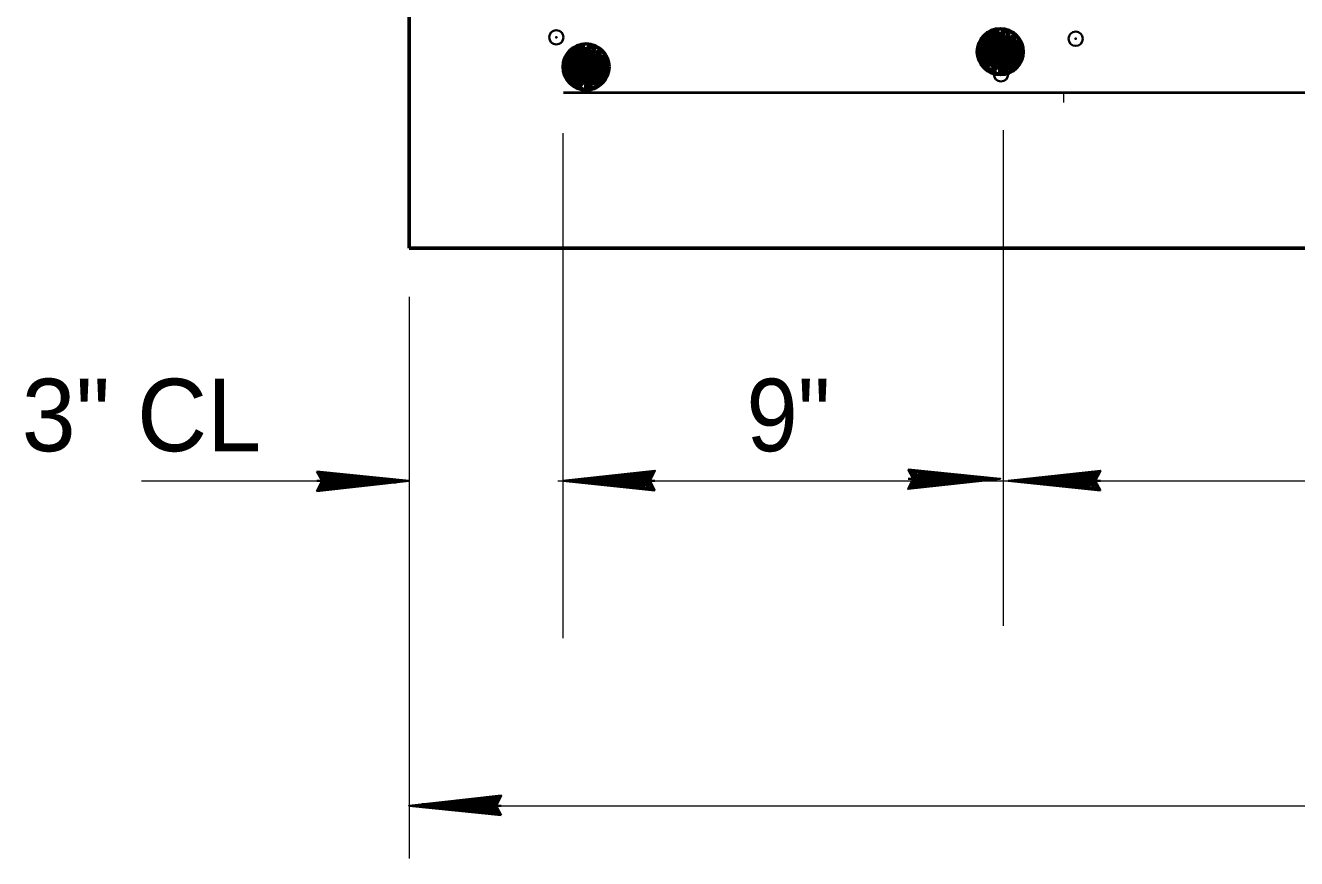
# Model space of a CAD drawing. Extents: x 4.49 to 7.69, y 0.28 to 2.27.
# Drawn here: x 5.8123 to 5.9583, y 1.8022 to 1.898 of the extents above; entities that cross this region are included whole.
import ezdxf
from ezdxf.enums import TextEntityAlignment as Align

# ---------------------------------------------------------------- set-up
doc = ezdxf.new("R2010")
doc.units = 0
doc.header["$LTSCALE"] = 0.0033
doc.header["$PDMODE"] = 32
doc.header["$PDSIZE"] = 0.00165
doc.layers.add('1', color=7, linetype='Continuous', lineweight=35)

msp = doc.modelspace()

# ---------------------------------------------------------------- linework, layer by layer
at = {"layer": '1', "lineweight": 60}
for p, q in [((5.856333, 1.872333), (5.856333, 1.955667)), ((5.922417, 1.8965), (5.92225, 1.893583)), ((5.922667, 1.8965), (5.922417, 1.893583)), ((5.922833, 1.8965), (5.922667, 1.8935)), ((5.923, 1.8965), (5.92275, 1.8935)), ((5.923167, 1.8965), (5.923, 1.8935)), ((5.923417, 1.8965), (5.92325, 1.8935)), ((5.923667, 1.8965), (5.923417, 1.8935)), ((5.92375, 1.896417), (5.923583, 1.8935)), ((5.923917, 1.896417), (5.92375, 1.8935)), ((5.924083, 1.896417), (5.923917, 1.8935)), ((5.924333, 1.896417), (5.924083, 1.8935)), ((5.9245, 1.896417), (5.924333, 1.8935)), ((5.92475, 1.896333), (5.9245, 1.893417)), ((5.925, 1.896333), (5.92475, 1.893417)), ((5.925167, 1.896333), (5.925, 1.893417)), ((5.92525, 1.896333), (5.925083, 1.893417)), ((5.925417, 1.896333), (5.92525, 1.893417)), ((5.9255, 1.896333), (5.925333, 1.893417)), ((5.92575, 1.89625), (5.9255, 1.893333)), ((5.925917, 1.89625), (5.92575, 1.893333)), ((5.926083, 1.89625), (5.925833, 1.893333)), ((5.92625, 1.89625), (5.926083, 1.893333)), ((5.9265, 1.89625), (5.926333, 1.893333)), ((5.92675, 1.894333), (5.926583, 1.896167)), ((5.874833, 1.89475), (5.874667, 1.891833)), ((5.875083, 1.89475), (5.874833, 1.891833)), ((5.87525, 1.89475), (5.875083, 1.89175)), ((5.875417, 1.89475), (5.875167, 1.89175)), ((5.875583, 1.89475), (5.875417, 1.89175)), ((5.875833, 1.89475), (5.875667, 1.89175)), ((5.876083, 1.89475), (5.875833, 1.89175)), ((5.876167, 1.894667), (5.876, 1.89175)), ((5.876333, 1.894667), (5.876167, 1.89175)), ((5.8765, 1.894667), (5.876333, 1.89175)), ((5.87675, 1.894667), (5.8765, 1.89175)), ((5.876917, 1.894667), (5.87675, 1.89175)), ((5.877167, 1.894583), (5.876917, 1.891667)), ((5.877417, 1.894583), (5.877167, 1.891667)), ((5.877583, 1.894583), (5.877417, 1.891667)), ((5.877667, 1.894583), (5.8775, 1.891667)), ((5.877833, 1.894583), (5.877667, 1.891667)), ((5.877917, 1.894583), (5.87775, 1.891667)), ((5.878167, 1.8945), (5.877917, 1.891583)), ((5.878333, 1.8945), (5.878167, 1.891583)), ((5.8785, 1.8945), (5.87825, 1.891583)), ((5.878667, 1.8945), (5.8785, 1.891583)), ((5.878917, 1.8945), (5.87875, 1.891583)), ((5.879167, 1.892583), (5.879, 1.894417)), ((5.92675, 1.894333), (5.922, 1.893583)), ((5.879167, 1.892583), (5.874417, 1.891833))]:
    msp.add_line(p, q, dxfattribs=at)
at = {"layer": '1', "lineweight": 40}
for p, q in [((5.9245, 1.896), (5.925833, 1.897)), ((5.926583, 1.896167), (5.925333, 1.897333)), ((5.879, 1.894417), (5.87775, 1.895583)), ((5.922167, 1.8965), (5.92675, 1.894333)), ((5.922417, 1.896083), (5.926333, 1.895333)), ((5.922417, 1.895917), (5.926333, 1.895167)), ((5.922417, 1.895667), (5.92625, 1.894917)), ((5.9225, 1.8965), (5.926417, 1.895833)), ((5.9225, 1.896333), (5.926417, 1.895583)), ((5.922583, 1.896833), (5.926417, 1.896167)), ((5.874583, 1.89475), (5.879167, 1.892583)), ((5.874833, 1.894333), (5.87875, 1.893583)), ((5.874833, 1.894167), (5.87875, 1.893417)), ((5.874917, 1.89475), (5.878833, 1.894083)), ((5.874917, 1.894583), (5.878833, 1.893833)), ((5.875, 1.895083), (5.878833, 1.894417)), ((5.876917, 1.89425), (5.87825, 1.89525)), ((5.922083, 1.89425), (5.926, 1.8935)), ((5.922083, 1.894083), (5.925917, 1.893333)), ((5.922167, 1.894667), (5.926083, 1.893917)), ((5.92225, 1.895083), (5.926083, 1.894333)), ((5.92225, 1.894917), (5.926083, 1.894167)), ((5.922333, 1.8955), (5.926167, 1.894833)), ((5.922333, 1.895333), (5.926167, 1.894583)), ((5.874583, 1.892917), (5.8785, 1.892167)), ((5.874667, 1.893333), (5.8785, 1.892583)), ((5.874667, 1.893167), (5.8785, 1.892417)), ((5.87475, 1.89375), (5.878583, 1.893083)), ((5.87475, 1.893583), (5.878583, 1.892833)), ((5.874833, 1.893917), (5.878667, 1.893167)), ((5.922, 1.89375), (5.925833, 1.893)), ((5.922, 1.893583), (5.925833, 1.892833)), ((5.922083, 1.893833), (5.925917, 1.893167)), ((5.926333, 1.893333), (5.922583, 1.892917)), ((5.874417, 1.892), (5.87825, 1.89125)), ((5.874417, 1.891833), (5.87825, 1.891083)), ((5.8745, 1.8925), (5.878417, 1.89175)), ((5.8745, 1.892333), (5.878333, 1.891583)), ((5.8745, 1.892083), (5.878333, 1.891417)), ((5.87875, 1.891583), (5.875, 1.891167)), ((5.874083, 1.89025), (6.17175, 1.89025))]:
    msp.add_line(p, q, dxfattribs=at)
at = {"layer": '1', "lineweight": 13}
for p, q in [((5.9315, 1.89025), (5.9315, 1.889083)), ((5.874, 1.885583), (5.874, 1.8275)), ((5.924583, 1.885917), (5.924583, 1.828917)), ((5.856333, 1.86675), (5.856333, 1.802167)), ((5.825583, 1.845583), (5.846417, 1.845583)), ((5.873417, 1.845583), (6.170667, 1.845583)), ((5.860917, 1.80825), (6.187167, 1.80825))]:
    msp.add_line(p, q, dxfattribs=at)
at = {"layer": '1'}
for p, q in [((5.846, 1.846583), (5.853833, 1.845667)), ((5.846, 1.846583), (5.853833, 1.845667)), ((5.846, 1.8465), (5.853833, 1.845667)), ((5.846, 1.846417), (5.853833, 1.845583)), ((5.846, 1.846417), (5.853833, 1.845417)), ((5.884333, 1.846667), (5.877, 1.845833)), ((5.884333, 1.8465), (5.877, 1.84575)), ((5.884333, 1.846417), (5.877, 1.845583)), ((5.884417, 1.84625), (5.877083, 1.8455)), ((5.913833, 1.845167), (5.921167, 1.845917)), ((5.913917, 1.846833), (5.92175, 1.845917)), ((5.913917, 1.846833), (5.92175, 1.845917)), ((5.913917, 1.84675), (5.92175, 1.845917)), ((5.913917, 1.846667), (5.92175, 1.845833)), ((5.913917, 1.846667), (5.92175, 1.845667)), ((5.9355, 1.846667), (5.928167, 1.845833)), ((5.9355, 1.8465), (5.928167, 1.84575)), ((5.9355, 1.846417), (5.928167, 1.845583)), ((5.935583, 1.84625), (5.92825, 1.8455)), ((5.84575, 1.845583), (5.856333, 1.845583)), ((5.845917, 1.844917), (5.85325, 1.845667)), ((5.846, 1.84475), (5.853333, 1.845583)), ((5.846, 1.844667), (5.853333, 1.845417)), ((5.846, 1.8445), (5.853333, 1.845333)), ((5.884583, 1.845583), (5.874, 1.845583)), ((5.884333, 1.84475), (5.8765, 1.84575)), ((5.884333, 1.84475), (5.8765, 1.845583)), ((5.884333, 1.844583), (5.8765, 1.8455)), ((5.884333, 1.844583), (5.8765, 1.8455)), ((5.884333, 1.844667), (5.8765, 1.8455)), ((5.913667, 1.845833), (5.92425, 1.845833)), ((5.913917, 1.845), (5.92125, 1.845833)), ((5.913917, 1.844917), (5.92125, 1.845667)), ((5.913917, 1.84475), (5.92125, 1.845583)), ((5.93575, 1.845583), (5.925167, 1.845583)), ((5.9355, 1.84475), (5.927667, 1.84575)), ((5.9355, 1.84475), (5.927667, 1.845583)), ((5.9355, 1.844583), (5.927667, 1.8455)), ((5.9355, 1.844583), (5.927667, 1.8455)), ((5.9355, 1.844667), (5.927667, 1.8455)), ((5.866917, 1.80825), (5.856333, 1.80825)), ((5.866667, 1.807417), (5.858833, 1.808417)), ((5.866667, 1.807417), (5.858833, 1.80825)), ((5.866667, 1.80725), (5.858833, 1.808167)), ((5.866667, 1.80725), (5.858833, 1.808167)), ((5.866667, 1.807333), (5.858833, 1.808167)), ((5.866667, 1.809333), (5.859333, 1.8085)), ((5.866667, 1.809167), (5.859333, 1.808417)), ((5.866667, 1.809083), (5.859333, 1.80825)), ((5.86675, 1.808917), (5.859417, 1.808167))]:
    msp.add_line(p, q, dxfattribs=at)
at = {"layer": '1', "lineweight": 60}
for points in [[(6.189667, 1.955667), (6.189667, 1.872333), (5.856333, 1.872333)], [(5.925833, 1.892833), (5.925833, 1.897), (5.924167, 1.892333), (5.924667, 1.8975), (5.922583, 1.892917), (5.923333, 1.897417), (5.924917, 1.892417), (5.92175, 1.89575), (5.926583, 1.896167), (5.923333, 1.8925), (5.925333, 1.897333), (5.922167, 1.8965), (5.922, 1.893583)], [(5.922583, 1.892917), (5.924083, 1.895167), (5.921917, 1.896083), (5.923917, 1.8975), (5.924083, 1.89525), (5.92575, 1.892917), (5.92175, 1.89525), (5.9245, 1.896)], [(5.925333, 1.897333), (5.924083, 1.895167), (5.926333, 1.893333)], [(5.87825, 1.891083), (5.87825, 1.89525), (5.876583, 1.890583), (5.877083, 1.89575), (5.875, 1.891167), (5.87575, 1.895667), (5.877333, 1.890667), (5.874167, 1.894), (5.879, 1.894417), (5.87575, 1.89075), (5.87775, 1.895583), (5.874583, 1.89475), (5.874417, 1.891833)], [(5.875, 1.891167), (5.8765, 1.893417), (5.874333, 1.894333), (5.876333, 1.89575), (5.8765, 1.8935), (5.878167, 1.891167), (5.874167, 1.8935), (5.876917, 1.89425)], [(5.87775, 1.895583), (5.8765, 1.893417), (5.87875, 1.891583)], [(5.921583, 1.894833), (5.92675, 1.8955), (5.922167, 1.8965)], [(5.874, 1.893083), (5.879167, 1.89375), (5.874583, 1.89475)]]:
    msp.add_lwpolyline(points, dxfattribs=at)
at = {"layer": '1', "lineweight": 40}
for points in [[(5.922, 1.893583), (5.924083, 1.892333), (5.925833, 1.892833), (5.92675, 1.894333)], [(5.874417, 1.891833), (5.8765, 1.890583), (5.87825, 1.891083), (5.879167, 1.892583)]]:
    msp.add_lwpolyline(points, dxfattribs=at)
at = {"layer": '1'}
for points in [[(5.84575, 1.846667), (5.856333, 1.845583), (5.84575, 1.844417), (5.846333, 1.845583)], [(5.8465, 1.845667), (5.851167, 1.84575), (5.851167, 1.845667), (5.85025, 1.845667), (5.8465, 1.84575), (5.8495, 1.845833), (5.846333, 1.845917), (5.848583, 1.846), (5.846333, 1.846083), (5.849833, 1.845833), (5.8545, 1.845667), (5.853583, 1.845417), (5.854833, 1.845417), (5.8465, 1.845417), (5.848917, 1.84525), (5.846333, 1.84525), (5.851667, 1.845667), (5.846333, 1.845)], [(5.884583, 1.8445), (5.874, 1.845583), (5.884583, 1.84675), (5.884, 1.845583)], [(5.883833, 1.8455), (5.879167, 1.845417), (5.879167, 1.8455), (5.880083, 1.8455), (5.883833, 1.845417), (5.880833, 1.845333), (5.884, 1.84525), (5.88175, 1.845167), (5.884, 1.845083), (5.8805, 1.845333), (5.875833, 1.8455), (5.87675, 1.84575), (5.8755, 1.84575), (5.883833, 1.84575), (5.881417, 1.845917), (5.884, 1.845917), (5.878667, 1.8455), (5.884, 1.846167)], [(5.913667, 1.846917), (5.92425, 1.845833), (5.913667, 1.844667), (5.91425, 1.845833)], [(5.914417, 1.845917), (5.919083, 1.846), (5.919083, 1.845917), (5.918167, 1.845917), (5.914417, 1.846), (5.917417, 1.846083), (5.91425, 1.846167), (5.9165, 1.84625), (5.91425, 1.846333), (5.91775, 1.846083), (5.922417, 1.845917), (5.9215, 1.845667), (5.92275, 1.845667), (5.914417, 1.845667), (5.916833, 1.8455), (5.91425, 1.8455), (5.919583, 1.845917), (5.91425, 1.84525)], [(5.93575, 1.8445), (5.925167, 1.845583), (5.93575, 1.84675), (5.935167, 1.845583)], [(5.935, 1.8455), (5.930333, 1.845417), (5.930333, 1.8455), (5.93125, 1.8455), (5.935, 1.845417), (5.932, 1.845333), (5.935167, 1.84525), (5.932917, 1.845167), (5.935167, 1.845083), (5.931667, 1.845333), (5.927, 1.8455), (5.927917, 1.84575), (5.926667, 1.84575), (5.935, 1.84575), (5.932583, 1.845917), (5.935167, 1.845917), (5.929833, 1.8455), (5.935167, 1.846167)], [(5.866917, 1.807167), (5.856333, 1.80825), (5.866917, 1.809417), (5.866333, 1.80825)], [(5.866167, 1.808167), (5.8615, 1.808083), (5.8615, 1.808167), (5.862417, 1.808167), (5.866167, 1.808083), (5.863167, 1.808), (5.866333, 1.807917), (5.864083, 1.807833), (5.866333, 1.80775), (5.862833, 1.808), (5.858167, 1.808167), (5.859083, 1.808417), (5.857833, 1.808417), (5.866167, 1.808417), (5.86375, 1.808583), (5.866333, 1.808583), (5.861, 1.808167), (5.866333, 1.808833)]]:
    msp.add_lwpolyline(points, close=True, dxfattribs=at)
for points in [[(5.8465, 1.845667), (5.846083, 1.846417), (5.846333, 1.846167), (5.8465, 1.845833), (5.84675, 1.845917), (5.846583, 1.84625), (5.846417, 1.8455), (5.84625, 1.845), (5.846, 1.844583)], [(5.883833, 1.8455), (5.88425, 1.84475), (5.884, 1.845), (5.883833, 1.845333), (5.883583, 1.84525), (5.88375, 1.844917), (5.883917, 1.845667), (5.884083, 1.846167), (5.884333, 1.846583)], [(5.914417, 1.845917), (5.914, 1.846667), (5.91425, 1.846417), (5.914417, 1.846083), (5.914667, 1.846167), (5.9145, 1.8465), (5.914333, 1.84575), (5.914167, 1.84525), (5.913917, 1.844833)], [(5.935, 1.8455), (5.935417, 1.84475), (5.935167, 1.845), (5.935, 1.845333), (5.93475, 1.84525), (5.934917, 1.844917), (5.935083, 1.845667), (5.93525, 1.846167), (5.9355, 1.846583)], [(5.866167, 1.808167), (5.866583, 1.807417), (5.866333, 1.807667), (5.866167, 1.808), (5.865917, 1.807917), (5.866083, 1.807583), (5.86625, 1.808333), (5.866417, 1.808833), (5.866667, 1.80925)]]:
    msp.add_lwpolyline(points, dxfattribs=at)
at = {"layer": '1', "lineweight": 60}
for centre in [(5.92425, 1.894933), (5.876667, 1.893183)]:
    msp.add_circle(centre, 0.00264, dxfattribs=at)
at = {"layer": '1'}
for p in [(5.87325, 1.896583), (5.932917, 1.896417), (5.876167, 1.893333), (5.875583, 1.892167), (5.924333, 1.892333)]:
    msp.add_point(p, dxfattribs=at)

# ---------------------------------------------------------------- texts
msp.add_text('3" CL', height=0.008334, dxfattribs=at).set_placement((5.811833, 1.849))
at = {"layer": '1', "width": 0.95}
msp.add_text('9"', height=0.008334, dxfattribs=at).set_placement((5.899917, 1.849), align=Align.CENTER)

doc.saveas('drawing.dxf')
